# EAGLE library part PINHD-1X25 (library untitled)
PIN HEADER
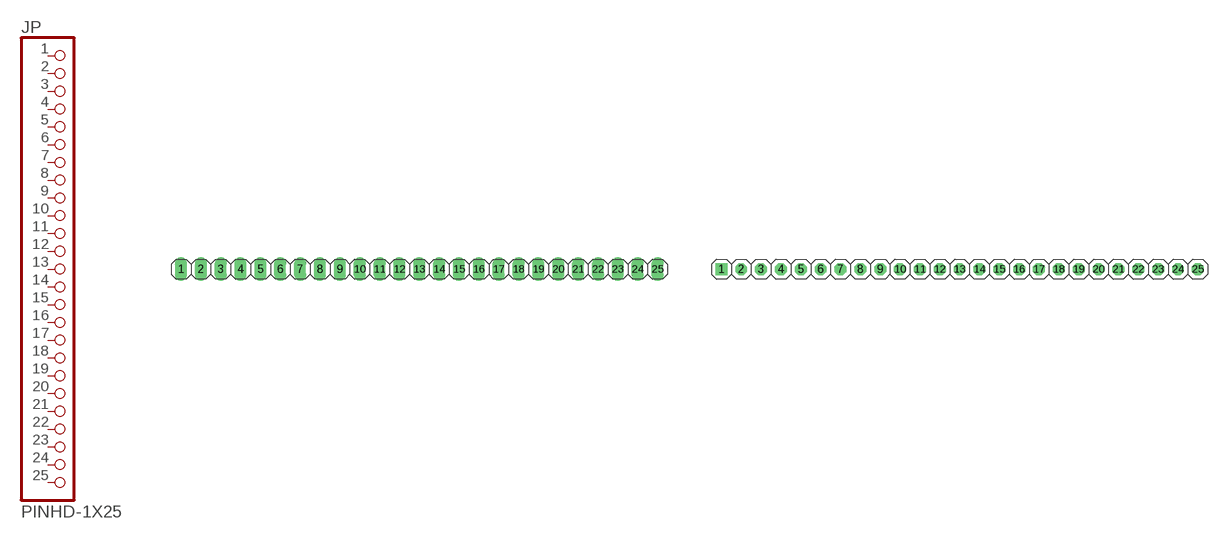
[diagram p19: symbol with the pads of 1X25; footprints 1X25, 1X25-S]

Designator prefix JP

## PINHD-1X25_2.54  [1X25]
1  1  pas
2  2  pas
3  3  pas
4  4  pas
5  5  pas
6  6  pas
7  7  pas
8  8  pas
9  9  pas
10  10  pas
11  11  pas
12  12  pas
13  13  pas
14  14  pas
15  15  pas
16  16  pas
17  17  pas
18  18  pas
19  19  pas
20  20  pas
21  21  pas
22  22  pas
23  23  pas
24  24  pas
25  25  pas

## PINHD-1X25_2.54-S  [1X25-S]
Pads as for 1X25

## PINHD-1X25_2802S-02G2  [2802S-02G2]
Pads as for 1X25

## PINHD-1X25_2.00  [1X25M]
Pads as for 1X25

## PINHD-1X25_2.54-90°  [1X25/90]
Pads as for 1X25

## PINHD-1X25_2.54-90°-S  [1X25/90-S]
Pads as for 1X25

## PINHD-1X25_2.54-SMD  [1X25SMD]
Pads as for 1X25

## PINHD-1X25_2.54-SMD-90°  [1X25SMD/90]
Pads as for 1X25

## Footprint 1X25 (pad centres in mm)
PIN HEADER - 2.54
drill 1.016 long: 1 -29.21,0; 2 -26.67,0; 3 -24.13,0; 4 -21.59,0; 5 -19.05,0; 6 -16.51,0; 7 -13.97,0; 8 -11.43,0; 9 -8.89,0; 10 -6.35,0; 11 -3.81,0; 12 -1.27,0; 13 1.27,0; 14 3.81,0; 15 6.35,0; 16 8.89,0; 17 11.43,0; 18 13.97,0; 19 16.51,0; 20 19.05,0; 21 21.59,0; 22 24.13,0; 23 26.67,0; 24 29.21,0; 25 31.75,0

## Footprint 1X25-S (pad centres in mm)
PIN HEADER - 2.54
drill 1.016 square: 1 -29.21,0
drill 1.016 octagon: 2 -26.67,0; 3 -24.13,0; 4 -21.59,0; 5 -19.05,0; 6 -16.51,0; 7 -13.97,0; 8 -11.43,0; 9 -8.89,0; 10 -6.35,0; 11 -3.81,0; 12 -1.27,0; 13 1.27,0; 14 3.81,0; 15 6.35,0; 16 8.89,0; 17 11.43,0; 18 13.97,0; 19 16.51,0; 20 19.05,0; 21 21.59,0; 22 24.13,0; 23 26.67,0; 24 29.21,0; 25 31.75,0

## Footprint 2802S-02G2 (pad centres in mm)
2mm Center - .020 inch Square Pin - Single Row Straight Header Source: http://www.commcon.com/main
drill 0.8 pad 1.422 round: 1 -24,0; 2 -22,0; 3 -20,0; 4 -18,0; 5 -16,0; 6 -14,0; 7 -12,0; 8 -10,0; 9 -8,0; 10 -6,0; 11 -4,0; 12 -2,0; 13 0,0; 14 2,0; 15 4,0; 16 6,0; 17 8,0; 18 10,0; 19 12,0; 20 14,0; 21 16,0; 22 18,0; 23 20,0; 24 22,0; 25 24,0

## Footprint 1X25M (pad centres in mm)
PIN HEADER - 2
drill 0.914 square: 1 -24,0
drill 0.914 round: 2 -22,0; 3 -20,0; 4 -18,0; 5 -16,0; 6 -14,0; 7 -12,0; 8 -10,0; 9 -8,0; 10 -6,0; 11 -4,0; 12 -2,0; 13 0,0; 14 2,0; 15 4,0; 16 6,0; 17 8,0; 18 10,0; 19 12,0; 20 14,0; 21 16,0; 22 18,0; 23 20,0; 24 22,0; 25 24,0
